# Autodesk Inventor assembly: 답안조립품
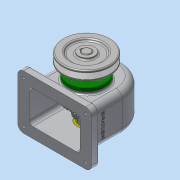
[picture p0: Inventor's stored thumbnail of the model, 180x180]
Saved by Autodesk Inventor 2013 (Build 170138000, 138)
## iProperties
Created: 2016-10
Part Number: 답안조립품
Document SubType Name: Assembly
Designer: dgall
Author: dgall
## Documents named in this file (15)
- C:\Users\dgall\Desktop\461007V1008\답안조립품.iam
- C:\Users\dgall\Desktop\461007V1008\본체.ipt
- C:\Users\dgall\Desktop\461007V1008\V-벨트풀리.ipt
- C:\Users\dgall\Desktop\461007V1008\뒤커버.ipt
- C:\Users\dgall\Desktop\461007V1008\멈춤나사 - M4x10.ipt
- C:\Users\dgall\Desktop\461007V1008\베어링 6203.ipt
- C:\Users\dgall\Desktop\461007V1008\볼트 M3 x 8.ipt
- C:\Users\dgall\Desktop\461007V1008\볼트 M3 x 10.ipt
- C:\Users\dgall\Desktop\461007V1008\부시.ipt
- C:\Users\dgall\Desktop\461007V1008\스퍼기어.ipt
- C:\Users\dgall\Desktop\461007V1008\앞커버.ipt
- C:\Users\dgall\Desktop\461007V1008\오일씰 28 40 8.ipt
- C:\Users\dgall\Desktop\461007V1008\축.ipt
- C:\Users\dgall\Desktop\461007V1008\키 - 5 x 5 x 18.ipt
- C:\Users\dgall\Desktop\461007V1008\키 - 6 x 6 x 22.ipt
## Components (9 placed, 3 different names)
1. V-벨트풀리:1
2. ISO 4762 M3 x 8:1
3. ISO 4762 M3 x 8:2
4. ISO 4762 M3 x 8:3
5. ISO 4762 M3 x 8:4
6. ISO 4762 M3 x 10:1
7. ISO 4762 M3 x 10:2
8. ISO 4762 M3 x 10:3
9. ISO 4762 M3 x 10:4
